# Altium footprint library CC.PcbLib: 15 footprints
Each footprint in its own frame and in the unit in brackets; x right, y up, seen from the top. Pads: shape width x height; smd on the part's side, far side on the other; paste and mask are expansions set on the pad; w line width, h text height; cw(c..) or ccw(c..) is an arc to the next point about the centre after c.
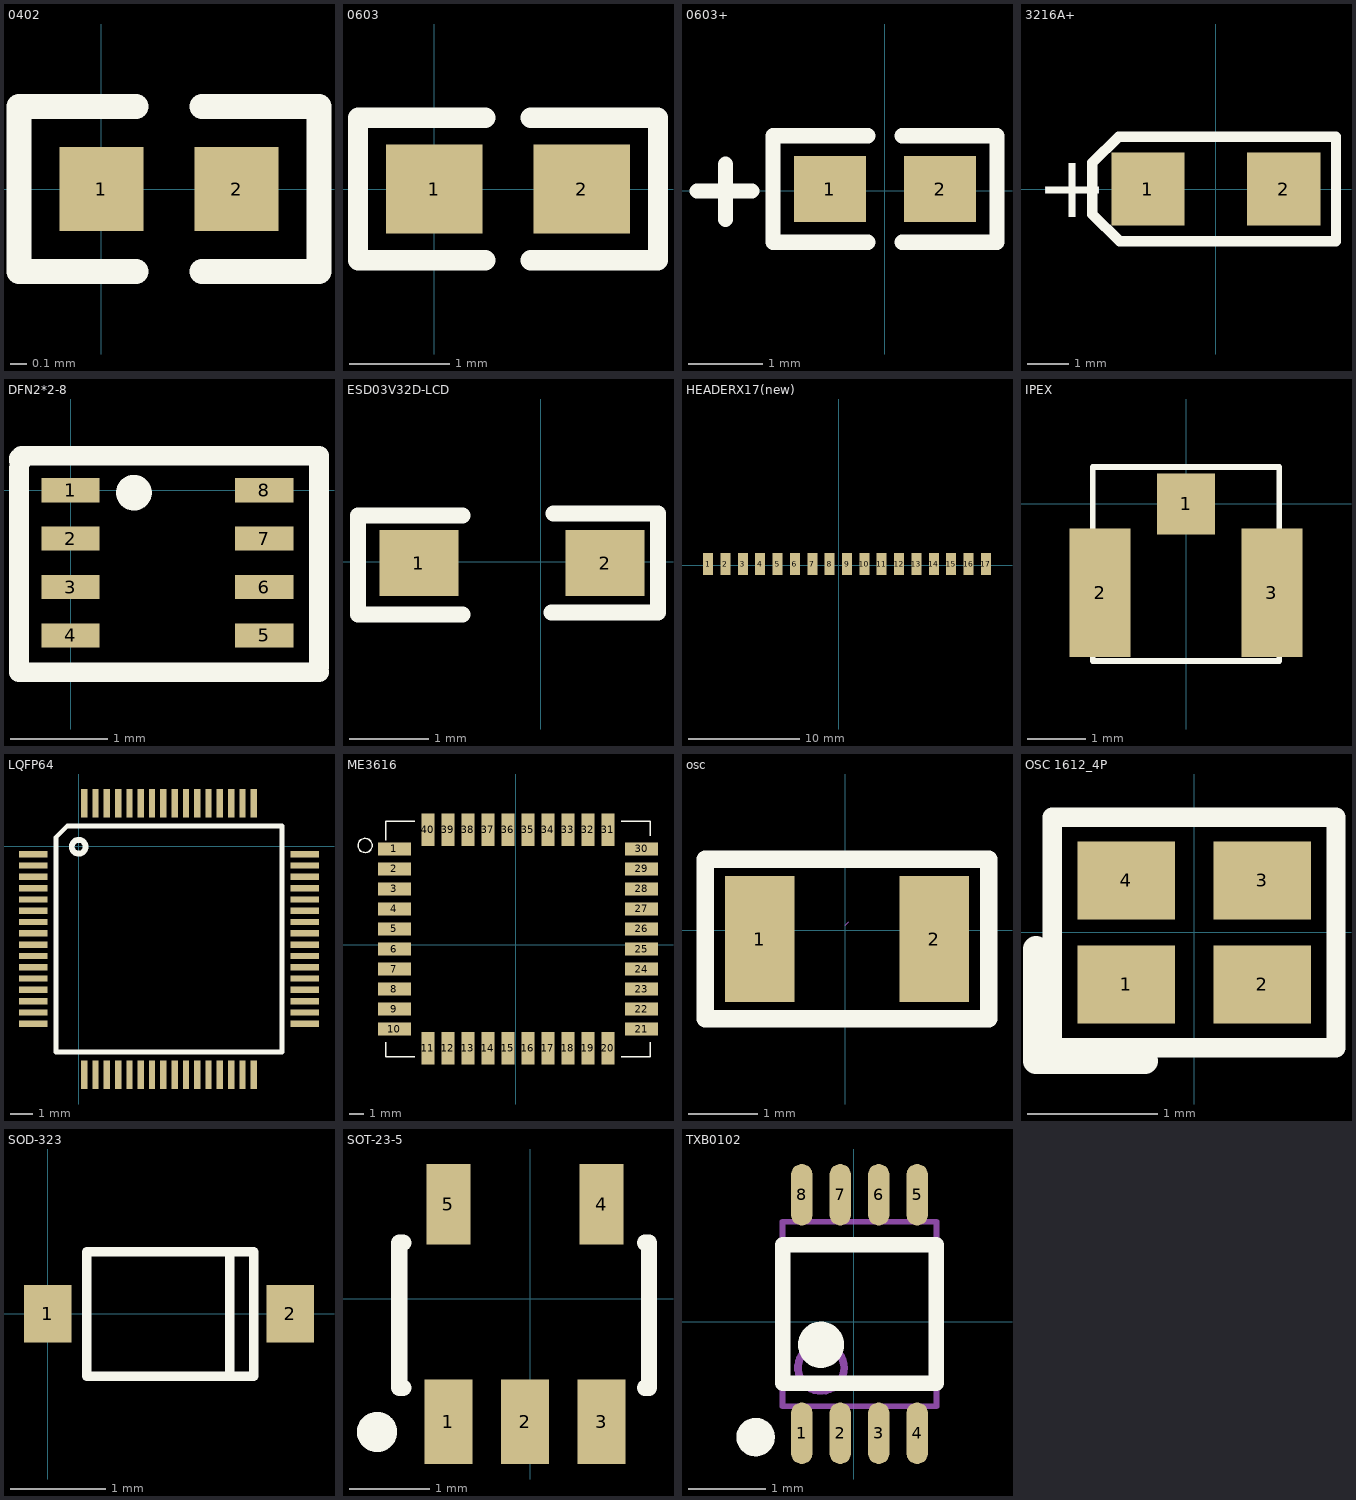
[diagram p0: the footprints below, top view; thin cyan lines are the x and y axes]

## 0402 [mm]
pads (2):
  rect 0.51x0.51 smd: 1(0,0) 2(0.82,0)
Top Overlay:
  lines w0.152: 0.21,-0.5 -0.5,-0.5 -0.5,0.5 0.21,0.5 ; 0.61,-0.5 1.32,-0.5 1.32,0.5 0.61,0.5

## 0603 [mil]
pads (2):
  rect 38x35 smd: 1(0,0) 2(58,0)
Top Overlay:
  lines w8: 20,-28 -30,-28 -30,28 20,28 ; 38,-28 88,-28 88,28 38,28

## 0603+ [mil]
pads (2):
  rect 38x35 smd: 1(-29,1) 2(29,1)
Top Overlay:
  lines w8: -99,0 -70,0 ; -84,-15 -84,14 ; -9,-27 -59,-27 -59,29 -9,29 ; 9,-27 59,-27 59,29 9,29

## 3216A+ [mil]
pads (2):
  rect 70x70 smd: 1(-65,0) 2(65,0)
Top Overlay:
  lines w10: -118,-24 -118,25 -93,50 115,50 115,-50 -92,-50 -118,-24
  text "+" at -172,-27 h60

## DFN2*2-8 [mm]
pads (8):
  rect 0.6x0.25 smd: 1(0,0) 2(0,-0.5) 3(0,-1) 4(0,-1.5) 5(2,-1.5) 6(2,-1) 7(2,-0.5) 8(2,0)
Top Overlay:
  circle w0.254: c0.654,-0.025 r0.057
  lines w0.203: -0.533,0.229 -0.533,-1.88 2.565,-1.88 ; -0.533,0.305 -0.533,0.33 -0.508,0.305 -0.508,0.356 2.565,0.356 2.565,-1.829

## ESD03V32D-LCD [mm]
pads (2):
  rect 1x0.83 smd: 1(-1.542,-0.014) 2(0.818,-0.014)
Top Overlay:
  lines w0.203: -0.987,-0.664 -2.312,-0.664 -2.312,0.586 -0.987,0.586 ; 0.138,-0.639 1.488,-0.639 1.488,0.611 0.163,0.611

## HEADERX17(new) [mm]
pads (17):
  rect 0.9x2 smd: 1(-11.733,0.102) 2(-10.173,0.102) 3(-8.613,0.102) 4(-7.053,0.102) 5(-5.493,0.102) 6(-3.933,0.102) 7(-2.373,0.102) 8(-0.813,0.102) 9(0.747,0.102) 10(2.307,0.102) 11(3.867,0.102) 12(5.427,0.102) 13(6.987,0.102) 14(8.547,0.102) 15(10.107,0.102) 16(11.667,0.102) 17(13.227,0.102)

## IPEX [mm]
pads (3):
  rect 1x1.05 smd: 1(0,0)
  rect 1.05x2.2 smd: 2(-1.475,-1.525) 3(1.475,-1.525)
Top Overlay:
  lines w0.1: -1.6,-2.7 1.6,-2.7 1.6,0.635 -1.6,0.635 -1.6,-2.7

## LQFP64 [mm]
pads (64):
  rect 1.27x0.28 smd: 1(-2.007,-0.356) 2(-2.007,-0.856) 3(-2.007,-1.356) 4(-2.007,-1.856) 5(-2.007,-2.356) 6(-2.007,-2.856) 7(-2.007,-3.356) 8(-2.007,-3.856) 9(-2.007,-4.356) 10(-2.007,-4.856) 11(-2.007,-5.356) 12(-2.007,-5.856) 13(-2.007,-6.356) 14(-2.007,-6.856) 15(-2.007,-7.356) 16(-2.007,-7.856) 33(9.993,-7.856) 34(9.993,-7.356) 35(9.993,-6.856) 36(9.993,-6.356) 37(9.993,-5.856) 38(9.993,-5.356) 39(9.993,-4.856) 40(9.993,-4.356) 41(9.993,-3.856) 42(9.993,-3.356) 43(9.993,-2.856) 44(9.993,-2.356) 45(9.993,-1.856) 46(9.993,-1.356) 47(9.993,-0.856) 48(9.993,-0.356)
  rect 0.28x1.27 smd: 17(0.243,-10.106) 18(0.743,-10.106) 19(1.243,-10.106) 20(1.743,-10.106) 21(2.243,-10.106) 22(2.743,-10.106) 23(3.243,-10.106) 24(3.743,-10.106) 25(4.243,-10.106) 26(4.743,-10.106) 27(5.243,-10.106) 28(5.743,-10.106) 29(6.243,-10.106) 30(6.743,-10.106) 31(7.243,-10.106) 32(7.743,-10.106) 49(7.743,1.894) 50(7.243,1.894) 51(6.743,1.894) 52(6.243,1.894) 53(5.743,1.894) 54(5.243,1.894) 55(4.743,1.894) 56(4.243,1.894) 57(3.743,1.894) 58(3.243,1.894) 59(2.743,1.894) 60(2.243,1.894) 61(1.743,1.894) 62(1.243,1.894) 63(0.743,1.894) 64(0.243,1.894)
Top Overlay:
  circle w0.254: c-0.001,-0.025 r0.306
  lines w0.203: -1.007,-9.106 -1.007,0.394 -0.507,0.894 8.993,0.894 8.993,-9.106 -1.007,-9.106

## ME3616 [mm]
pads (40):
  rect 2.3x0.92 smd mask+0.05: 1(-8.509,6.706) 2(-8.509,5.306) 3(-8.509,3.906) 4(-8.509,2.506) 5(-8.509,1.106) 6(-8.509,-0.294) 7(-8.509,-1.694) 8(-8.509,-3.094) 9(-8.509,-4.494) 10(-8.509,-5.894) 21(8.791,-5.894) 22(8.791,-4.494) 23(8.791,-3.094) 24(8.791,-1.694) 25(8.791,-0.294) 26(8.791,1.106) 27(8.791,2.506) 28(8.791,3.906) 29(8.791,5.306) 30(8.791,6.706)
  rect 0.92x2.3 smd mask+0.05: 11(-6.159,-7.244) 12(-4.759,-7.244) 13(-3.359,-7.244) 14(-1.959,-7.244) 15(-0.559,-7.244) 16(0.841,-7.244) 17(2.241,-7.244) 18(3.641,-7.244) 19(5.041,-7.244) 20(6.441,-7.244) 31(6.441,8.056) 32(5.041,8.056) 33(3.641,8.056) 34(2.241,8.056) 35(0.841,8.056) 36(-0.559,8.056) 37(-1.959,8.056) 38(-3.359,8.056) 39(-4.759,8.056) 40(-6.159,8.056)
Top Overlay:
  circle w0.1: c-10.559,6.952 r0.496
  lines w0.1: -9.109,-6.814 -9.109,-7.844 -7.079,-7.844 ; -9.109,7.331 -9.109,8.206 -9.109,8.656 -8.659,8.656 -8.534,8.656 -7.079,8.656 ; 7.361,-7.844 9.391,-7.844 9.391,-6.814 ; 7.361,8.656 8.791,8.656 9.391,8.656 9.391,8.056 9.391,7.626

## osc [mm]
pads (2):
  rect 1x1.8 smd: 1(-1.225,-0.127) 2(1.275,-0.127)
Top Overlay:
  lines w0.254: -2.007,-1.27 -2.007,1.016 2.057,1.016 2.057,-1.27 -2.007,-1.27
Mechanical 15:
  lines w0.003: 0,0.07 0.051,0.121

## OSC 1612_4P [mm]
pads (4):
  rect 0.75x0.6 smd: 1(-0.525,-0.4) 2(0.525,-0.4) 3(0.525,0.4) 4(-0.525,0.4)
Top Overlay:
  lines w0.15: -1.092,-0.889 -1.092,0.889 1.092,0.889 1.092,-0.889 -1.092,-0.889
  lines w0.2: -1.219,-0.991 -0.381,-0.991 ; -1.219,-0.965 -1.219,-0.127
3D body: height 0.35, standoff -0.02, extent -0.8,-0.635 0.8,0.565

## SOD-323 [mm]
pads (2):
  rect 0.5x0.6 smd: 1(0,0) 2(2.54,0)
Top Overlay:
  lines w0.1: 1.905,-0.651 1.905,0.649 ; 0.409,-0.651 0.409,0.649 2.159,0.649 2.159,-0.649 2.157,-0.651 0.409,-0.651
3D body: height 0.9, standoff -0.09, extent 0.02,-0.635 2.52,0.615

## SOT-23-5 [mm]
pads (5):
  rect 0.6x1.05 smd: 1(-1.016,-1.524) 2(-0.066,-1.524) 3(0.884,-1.524)
  rect 0.55x1 smd: 4(0.884,1.176) 5(-1.016,1.176)
Top Overlay:
  circle w0.25: c-1.903,-1.651 r0.125
  lines w0.203: -1.576,-1.103 -1.626,-1.103 -1.626,0.697 -1.576,0.697 ; 1.424,-1.103 1.474,-1.103 1.474,0.697 1.424,0.697
3D body: height 1.09, standoff -0.01, extent -1.502,-1.527 1.397,1.273

## TXB0102 [mm]
pads (8):
  oval 0.28x0.8 smd mask+0.051: 1(-0.674,-1.448) 2(-0.174,-1.448) 3(0.326,-1.448) 4(0.826,-1.448) 5(0.826,1.652) 6(0.326,1.652) 7(-0.174,1.652) 8(-0.674,1.652)
Top Overlay:
  circle w0.35: c-0.424,-0.298 r0.125
  circle w0.25: c-1.274,-1.498 r0.125
  lines w0.2: -0.924,-0.798 -0.924,1.002 1.076,1.002 1.076,-0.798 -0.924,-0.798
Mechanical 13:
  circle w0.1: c-0.424,-0.598 r0.3
  lines w0.076: -0.924,-1.098 -0.924,1.302 1.076,1.302 1.076,-1.098 -0.924,-1.098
